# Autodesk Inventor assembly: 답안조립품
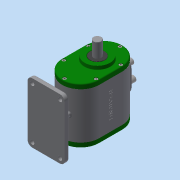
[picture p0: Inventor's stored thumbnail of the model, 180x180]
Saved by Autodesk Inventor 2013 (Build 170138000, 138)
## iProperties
Created: 2018-10
Part Number: 답안조립품
Document SubType Name: Assembly
Designer: Administrator
Author: Administrator
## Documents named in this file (15)
- C:\Users\Administrator\Desktop\381007V1013\답안조립품.iam
- C:\Users\Administrator\Desktop\381007V1013\본체.ipt
- C:\Users\Administrator\Desktop\381007V1013\뒤커버.ipt
- C:\Users\Administrator\Desktop\381007V1013\메인축.ipt
- C:\Users\Administrator\Desktop\381007V1013\베어링 608.ipt
- C:\Users\Administrator\Desktop\381007V1013\베어링 6003.ipt
- C:\Users\Administrator\Desktop\381007V1013\볼트 M4.ipt
- C:\Users\Administrator\Desktop\381007V1013\부시.ipt
- C:\Users\Administrator\Desktop\381007V1013\서브축.ipt
- C:\Users\Administrator\Desktop\381007V1013\슬라이더.ipt
- C:\Users\Administrator\Desktop\381007V1013\앞커버.ipt
- C:\Users\Administrator\Desktop\381007V1013\오일실 8 22 7.ipt
- C:\Users\Administrator\Desktop\381007V1013\오일실 17 32 8.ipt
- C:\Users\Administrator\Desktop\381007V1013\가변스프링1.ipt
- C:\Users\Administrator\Desktop\381007V1013\가변스프링2.ipt
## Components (2 placed, 2 different names)
1. 가변스프링1:1
2. 가변스프링2:1
